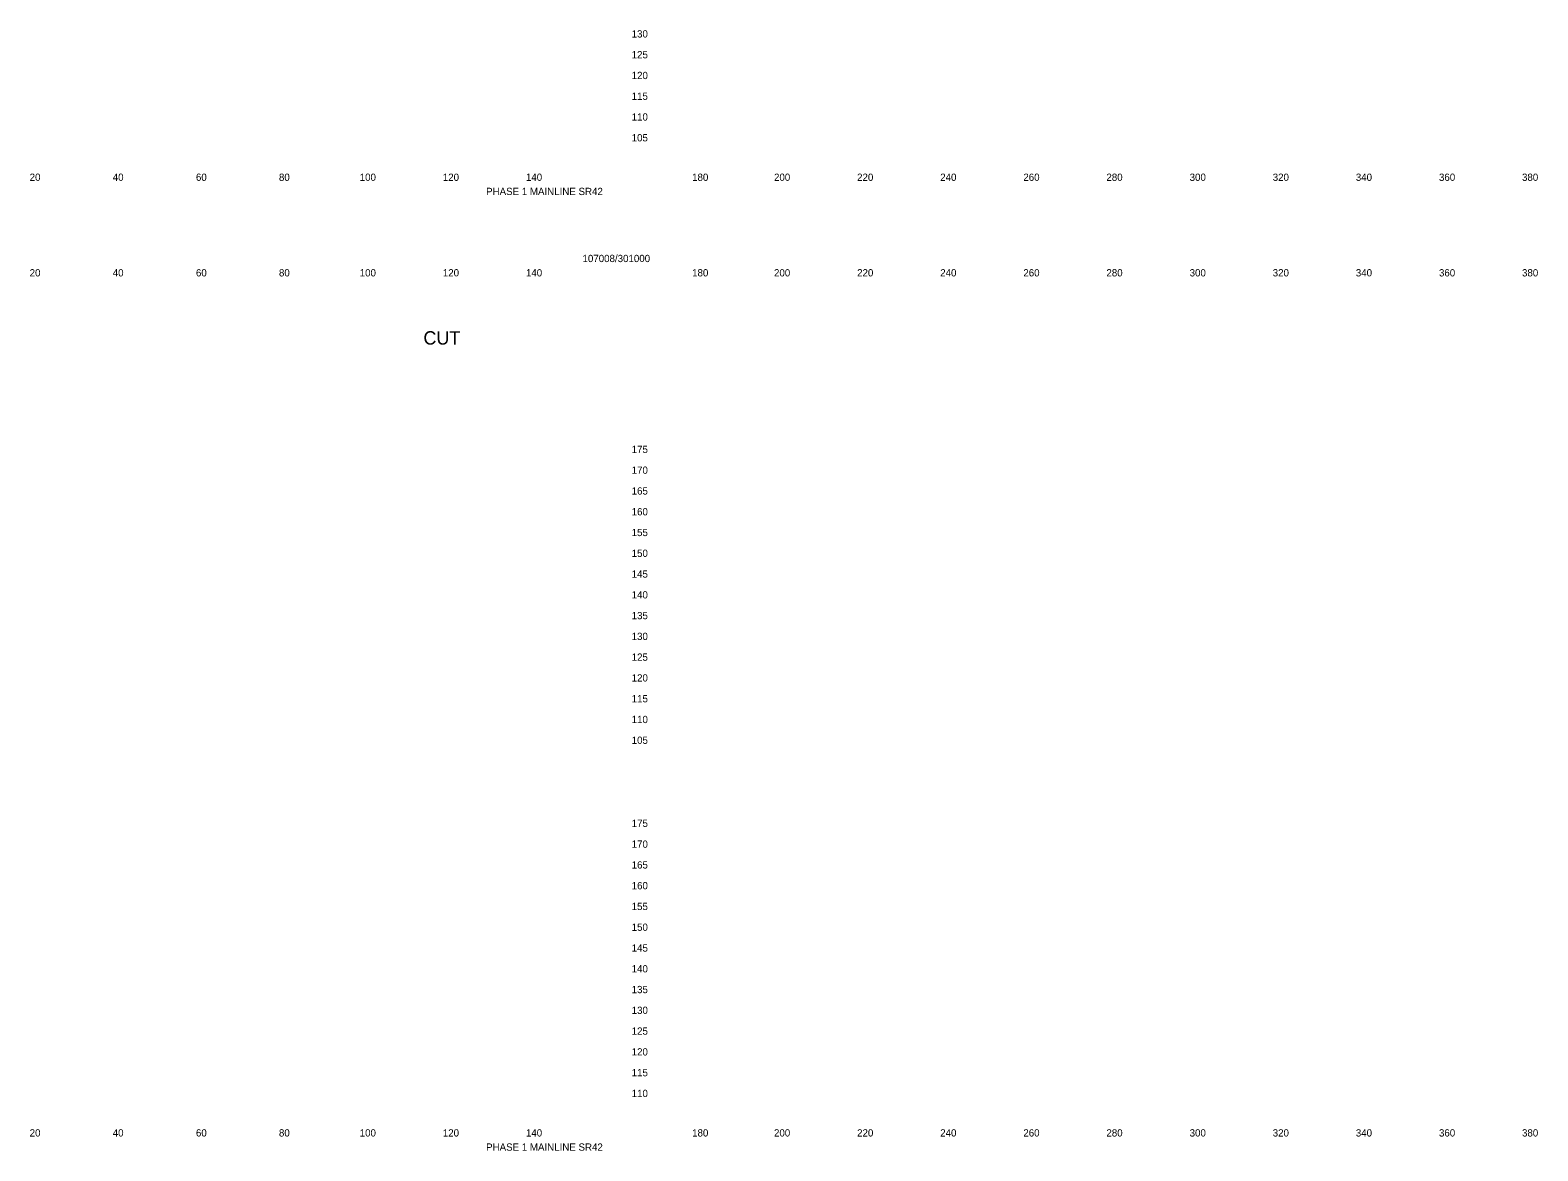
# Model space of a CAD drawing. Extents: x 21281 to 22024, y 6472 to 15198.
# Drawn here: x 21661.4 to 22024.2, y 10841.9 to 11111.6 of the extents above; entities that cross this region are included whole.
import ezdxf

# ---------------------------------------------------------------- set-up
doc = ezdxf.new("R2010")
doc.units = 0
doc.layers.add('XS_SHEET_LABELS_ELEVATION', color=7, linetype='Continuous')
doc.layers.add('XS_SHEET_LABELS_OFFSET', color=7, linetype='Continuous')

msp = doc.modelspace()

# ---------------------------------------------------------------- texts
at = {"layer": 'XS_SHEET_LABELS_ELEVATION'}
for s, p in [('  130  ', (21804.84, 11109.84)), ('  125  ', (21804.84, 11104.84)), ('  120  ', (21804.84, 11099.84)), ('  115  ', (21804.84, 11094.84)), ('  110  ', (21804.84, 11089.84)), ('  105  ', (21804.84, 11084.84)), ('  175  ', (21804.84, 11009.84)), ('  170  ', (21804.84, 11004.84)), ('  165  ', (21804.84, 10999.84)), ('  160  ', (21804.84, 10994.84)), ('  155  ', (21804.84, 10989.84)), ('  150  ', (21804.84, 10984.84)), ('  145  ', (21804.84, 10979.84)), ('  140  ', (21804.84, 10974.84)), ('  135  ', (21804.84, 10969.84)), ('  130  ', (21804.84, 10964.84)), ('  125  ', (21804.84, 10959.84)), ('  120  ', (21804.84, 10954.84)), ('  115  ', (21804.84, 10949.84)), ('  110  ', (21804.84, 10944.84)), ('  105  ', (21804.84, 10939.84)), ('  175  ', (21804.84, 10919.84)), ('  170  ', (21804.84, 10914.84)), ('  165  ', (21804.84, 10909.84)), ('  160  ', (21804.84, 10904.84)), ('  155  ', (21804.84, 10899.84)), ('  150  ', (21804.84, 10894.84)), ('  145  ', (21804.84, 10889.84)), ('  140  ', (21804.84, 10884.84)), ('  135  ', (21804.84, 10879.84)), ('  130  ', (21804.84, 10874.84)), ('  125  ', (21804.84, 10869.84)), ('  120  ', (21804.84, 10864.84)), ('  115  ', (21804.84, 10859.84)), ('  110  ', (21804.84, 10854.84))]:
    msp.add_text(s, height=1.75, dxfattribs=at).set_placement(p)
at = {"layer": 'XS_SHEET_LABELS_OFFSET'}
for s, height, p in [('  20  ', 1.75, (21659.95, 11075.34)), ('  40  ', 1.75, (21679.95, 11075.34)), ('  60  ', 1.75, (21699.97, 11075.34)), ('  80  ', 1.75, (21719.95, 11075.34)), ('  100  ', 1.75, (21739.39, 11075.34)), ('  120  ', 1.75, (21759.39, 11075.34)), ('  140  ', 1.75, (21779.39, 11075.34)), ('  180  ', 1.75, (21819.39, 11075.34)), ('  200  ', 1.75, (21839.1, 11075.34)), ('  220  ', 1.75, (21859.1, 11075.34)), ('  240  ', 1.75, (21879.1, 11075.34)), ('  260  ', 1.75, (21899.11, 11075.34)), ('  280  ', 1.75, (21919.1, 11075.34)), ('  300  ', 1.75, (21939.13, 11075.34)), ('  320  ', 1.75, (21959.13, 11075.34)), ('  340  ', 1.75, (21979.13, 11075.34)), ('  360  ', 1.75, (21999.14, 11075.34)), ('  380  ', 1.75, (22019.13, 11075.34)), ('PHASE 1 MAINLINE SR42', 1.75, (21771.11, 11071.92)), ('107008/301000', 1.75, (21794.31, 11055.79)), ('  20  ', 1.75, (21659.95, 11052.34)), ('  40  ', 1.75, (21679.95, 11052.34)), ('  60  ', 1.75, (21699.97, 11052.34)), ('  80  ', 1.75, (21719.95, 11052.34)), ('  100  ', 1.75, (21739.39, 11052.34)), ('  120  ', 1.75, (21759.39, 11052.34)), ('  140  ', 1.75, (21779.39, 11052.34)), ('  180  ', 1.75, (21819.39, 11052.34)), ('  200  ', 1.75, (21839.1, 11052.34)), ('  220  ', 1.75, (21859.1, 11052.34)), ('  240  ', 1.75, (21879.1, 11052.34)), ('  260  ', 1.75, (21899.11, 11052.34)), ('  280  ', 1.75, (21919.1, 11052.34)), ('  300  ', 1.75, (21939.13, 11052.34)), ('  320  ', 1.75, (21959.13, 11052.34)), ('  340  ', 1.75, (21979.13, 11052.34)), ('  360  ', 1.75, (21999.14, 11052.34)), ('  380  ', 1.75, (22019.13, 11052.34)), ('CUT', 3.222, (21756.03, 11035.94)), ('  20  ', 1.75, (21659.95, 10845.34)), ('  40  ', 1.75, (21679.95, 10845.34)), ('  60  ', 1.75, (21699.97, 10845.34)), ('  80  ', 1.75, (21719.95, 10845.34)), ('  100  ', 1.75, (21739.39, 10845.34)), ('  120  ', 1.75, (21759.39, 10845.34)), ('  140  ', 1.75, (21779.39, 10845.34)), ('  180  ', 1.75, (21819.39, 10845.34)), ('  200  ', 1.75, (21839.1, 10845.34)), ('  220  ', 1.75, (21859.1, 10845.34)), ('  240  ', 1.75, (21879.1, 10845.34)), ('  260  ', 1.75, (21899.11, 10845.34)), ('  280  ', 1.75, (21919.1, 10845.34)), ('  300  ', 1.75, (21939.13, 10845.34)), ('  320  ', 1.75, (21959.13, 10845.34)), ('  340  ', 1.75, (21979.13, 10845.34)), ('  360  ', 1.75, (21999.14, 10845.34)), ('  380  ', 1.75, (22019.13, 10845.34)), ('PHASE 1 MAINLINE SR42', 1.75, (21771.11, 10841.92))]:
    msp.add_text(s, height=height, dxfattribs=at).set_placement(p)

doc.saveas('drawing.dxf')
